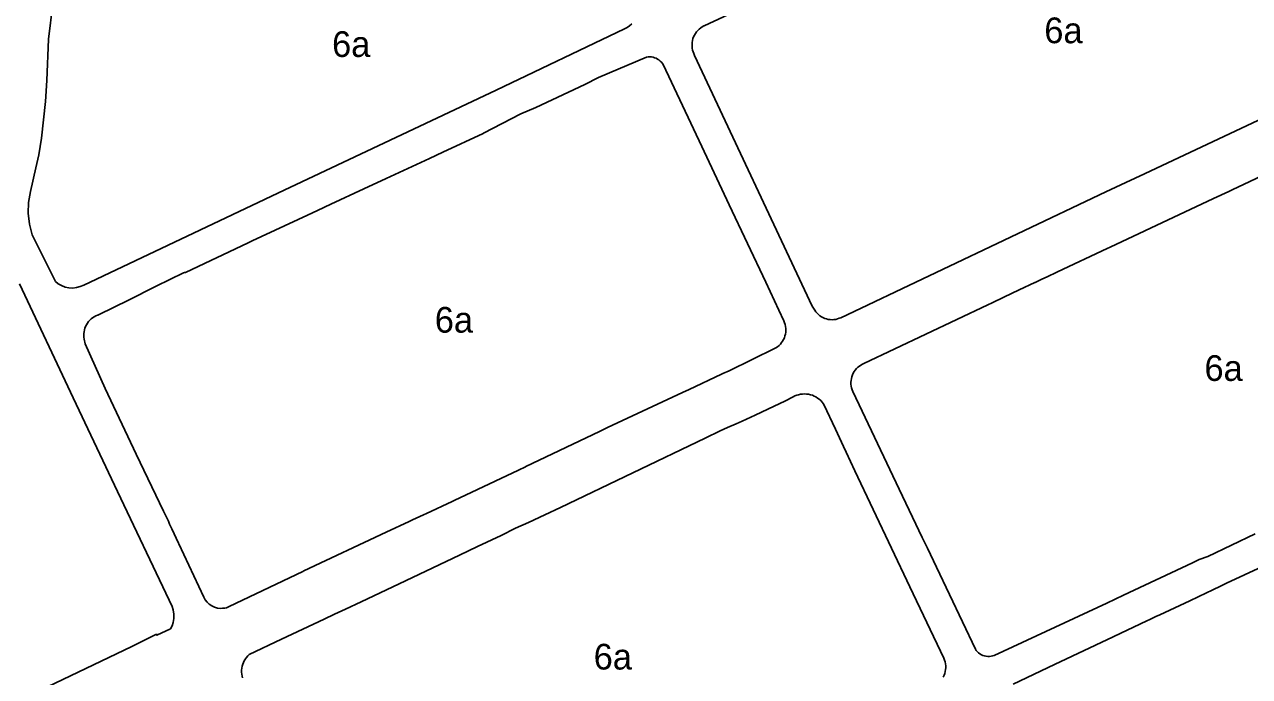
# Model space of a CAD drawing. Extents: x 598968 to 613553, y 4409678 to 4430833.
# Drawn here: x 606081 to 606653, y 4415842 to 4416147 of the extents above; entities that cross this region are included whole.
import ezdxf

# ---------------------------------------------------------------- set-up
doc = ezdxf.new("R2010")
doc.units = 0
doc.layers.add('1', color=7, linetype='Continuous')
doc.layers.add('Polígon industrial de Maó (naus i rafals) - ANNEX III D', color=7, linetype='Continuous')

msp = doc.modelspace()

# ---------------------------------------------------------------- linework, layer by layer
at = {"layer": '1'}
for points in [[(606714.9936, 4416129.6429), (606603.6249, 4416077.1617), (606594.915, 4416073.0516), (606585.6851, 4416068.7015), (606461.9065, 4416010.0001), (606461.2565, 4416009.7101), (606460.4265, 4416009.4301), (606459.5765, 4416009.2301), (606458.7165, 4416009.1101), (606457.8465, 4416009.0601), (606456.9766, 4416009.1001), (606456.1166, 4416009.2101), (606455.2666, 4416009.4), (606454.4366, 4416009.67), (606453.6366, 4416010.02), (606452.8666, 4416010.44), (606452.1466, 4416010.92), (606451.4766, 4416011.47), (606450.8466, 4416012.0799), (606450.2866, 4416012.7499), (606449.7866, 4416013.4599), (606448.6166, 4416015.3899), (606393.7268, 4416132.4777), (606393.3268, 4416133.2776), (606393.0168, 4416134.1176), (606392.7668, 4416134.9776), (606392.6067, 4416135.8576), (606392.5167, 4416136.7476), (606392.5167, 4416137.6376), (606392.5867, 4416138.5276), (606392.7467, 4416139.4076), (606392.9767, 4416140.2776), (606393.2867, 4416141.1176), (606393.6667, 4416141.9276), (606394.1167, 4416142.6976), (606394.6367, 4416143.4276), (606395.2267, 4416144.1076), (606395.8667, 4416144.7276), (606396.5567, 4416145.2876), (606397.2966, 4416145.7876), (606398.0866, 4416146.2276), (606398.1466, 4416146.2576), (606476.6657, 4416182.9285)], [(606364.3719, 4416147.226), (606363.3838, 4416146.2391), (606362.2488, 4416145.4255), (606360.997, 4416144.8067), (606301.1777, 4416116.2463), (606202.1687, 4416069.5752), (606108.6759, 4416025.2142), (606107.0466, 4416024.4959), (606105.3254, 4416024.04), (606103.5542, 4416023.8577), (606101.7762, 4416023.9534), (606100.0348, 4416024.3246), (606098.3724, 4416024.9625), (606096.8296, 4416025.8515), (606095.444, 4416026.9697), (606084.6908, 4416048.6742), (606083.329, 4416053.6255), (606082.7159, 4416058.724), (606082.8651, 4416063.857), (606083.7731, 4416068.9113), (606086.3129, 4416079.9566), (606087.6797, 4416086.0228), (606089.0208, 4416093.7918), (606090.8736, 4416110.9763), (606091.3879, 4416120.7991), (606092.2295, 4416140.1127), (606094.2594, 4416156.5825)], [(606655.2851, 4415909.1644), (606633.1953, 4415898.5342), (606629.2354, 4415897.0641), (606629.1654, 4415897.0441), (606626.0954, 4415895.6041), (606593.8857, 4415880.3836), (606586.0958, 4415876.7035), (606533.5164, 4415852.2929), (606532.7964, 4415852.0629), (606532.0364, 4415851.9129), (606531.2664, 4415851.8429), (606530.4964, 4415851.8529), (606529.7364, 4415851.9429), (606528.9765, 4415852.1029), (606528.2465, 4415852.3529), (606527.5465, 4415852.6628), (606526.8865, 4415853.0528), (606526.2565, 4415853.5128), (606525.6865, 4415854.0328), (606525.1765, 4415854.6028), (606524.7265, 4415855.2328), (606506.5265, 4415893.5721), (606502.3565, 4415902.352), (606499.9365, 4415907.4319), (606495.4665, 4415916.8517), (606489.2465, 4415929.9015), (606467.5166, 4415975.5806), (606467.1866, 4415976.3906), (606466.9366, 4415977.2406), (606466.7666, 4415978.1006), (606466.6666, 4415978.9806), (606466.6566, 4415979.8606), (606466.7166, 4415980.7405), (606466.8666, 4415981.6105), (606467.0866, 4415982.4605), (606467.3865, 4415983.2905), (606467.7565, 4415984.0905), (606468.2065, 4415984.8505), (606468.7165, 4415985.5705), (606469.2865, 4415986.2305), (606469.9265, 4415986.8505), (606470.6065, 4415987.4005), (606471.3465, 4415987.8905), (606472.1165, 4415988.3106), (606472.6165, 4415988.5406), (606530.4958, 4416015.9912), (606532.6058, 4416016.9912), (606537.9558, 4416019.5313), (606545.1757, 4416022.9614), (606552.4156, 4416026.3915), (606552.5956, 4416026.4815), (606555.5156, 4416027.8615), (606558.5355, 4416029.3015), (606562.4355, 4416031.1416), (606563.0955, 4416031.4516), (606586.3052, 4416042.3518), (606587.6752, 4416042.9918), (606603.805, 4416050.562), (606635.8947, 4416065.6324), (606642.9446, 4416068.9424), (606644.5646, 4416069.7025), (606726.6136, 4416108.3834)], [(606078.7075, 4416025.8831), (606103.7699, 4415972.6346), (606124.4582, 4415928.8511), (606148.533, 4415878.0414), (606149.8787, 4415875.2337), (606150.3831, 4415873.5761), (606150.7078, 4415871.5086), (606150.7243, 4415869.634), (606150.4163, 4415867.6769), (606149.8743, 4415866.151), (606149.1399, 4415864.7864), (606142.8299, 4415861.7363), (606142.6199, 4415862.1763), (606131.1401, 4415856.4662), (606073.9307, 4415829.0255)], [(606182.7796, 4415841.7872), (606182.5496, 4415842.6772), (606182.4096, 4415843.5972), (606182.3496, 4415844.5172), (606182.3596, 4415845.4472), (606182.4596, 4415846.3672), (606182.6296, 4415847.2772), (606182.8896, 4415848.1672), (606183.2196, 4415849.0272), (606183.6196, 4415849.8672), (606184.0896, 4415850.6572), (606184.6296, 4415851.4172), (606185.2296, 4415852.1172), (606185.8196, 4415852.6972), (606200.9894, 4415859.8473), (606220.8592, 4415869.2176), (606225.7691, 4415871.5276), (606230.8691, 4415873.9477), (606238.119, 4415877.3878), (606255.8689, 4415885.818), (606262.0688, 4415888.758), (606284.0786, 4415899.1984), (606292.4285, 4415903.1385), (606303.3884, 4415908.3186), (606310.1983, 4415911.7987), (606316.1983, 4415914.3688), (606323.7982, 4415917.9589), (606331.0781, 4415921.3889), (606398.5873, 4415953.7497), (606405.7272, 4415957.1898), (606409.0572, 4415958.6998), (606413.0471, 4415960.4399), (606415.9771, 4415961.7299), (606421.917, 4415964.53), (606430.8269, 4415968.7401), (606435.7869, 4415971.0801), (606439.6968, 4415973.0302), (606440.5168, 4415973.4402), (606441.3868, 4415973.7902), (606442.2668, 4415974.0602), (606443.1768, 4415974.2602), (606444.0968, 4415974.3702), (606445.0268, 4415974.4103), (606445.9568, 4415974.3603), (606446.8768, 4415974.2403), (606447.7868, 4415974.0403), (606448.6668, 4415973.7603), (606449.5268, 4415973.4003), (606450.3567, 4415972.9804), (606451.1367, 4415972.4804), (606451.8767, 4415971.9204), (606452.5667, 4415971.2904), (606453.1967, 4415970.6104), (606453.7667, 4415969.8804), (606454.0267, 4415969.5105), (606459.4267, 4415957.9707), (606463.2467, 4415949.7908), (606464.4367, 4415947.2609), (606468.5567, 4415938.441), (606494.1867, 4415884.3119), (606502.1066, 4415867.7323), (606510.0766, 4415851.0326), (606510.3966, 4415850.1726), (606510.6366, 4415849.2926), (606510.8066, 4415848.4026), (606510.8966, 4415847.4926), (606510.9066, 4415846.5826), (606510.8366, 4415845.6726), (606510.6866, 4415844.7726), (606510.4567, 4415843.8926), (606510.1567, 4415843.0327), (606509.7767, 4415842.2027)], [(606542.4164, 4415838.8932), (606561.6762, 4415848.0235), (606589.1059, 4415861.0338), (606589.3759, 4415861.1638), (606604.7557, 4415868.4539), (606606.1357, 4415869.114), (606609.0056, 4415870.474), (606610.8156, 4415871.324), (606624.7455, 4415877.8842), (606632.5954, 4415881.5843), (606635.1954, 4415882.8143), (606639.3553, 4415884.7743), (606641.9353, 4415885.9844), (606658.7351, 4415893.8947)]]:
    msp.add_lwpolyline(points, dxfattribs=at)
msp.add_lwpolyline([(606409.8568, 4416062.6987), (606426.9068, 4416026.5194), (606433.0368, 4416013.4896), (606435.4068, 4416008.4697), (606435.7368, 4416007.6397), (606435.9968, 4416006.7898), (606436.1768, 4416005.9198), (606436.2868, 4416005.0298), (606436.3068, 4416004.1398), (606436.2568, 4416003.2498), (606436.1168, 4416002.3698), (606435.9068, 4416001.5098), (606435.6168, 4416000.6698), (606435.2468, 4415999.8498), (606434.8168, 4415999.0798), (606434.3068, 4415998.3398), (606433.7368, 4415997.6598), (606433.1168, 4415997.0298), (606432.4368, 4415996.4498), (606431.7068, 4415995.9398), (606431.2968, 4415995.6998), (606409.8071, 4415985.1396), (606406.8371, 4415983.8795), (606406.337, 4415983.6448), (606391.1419, 4415976.5129), (606388.0774, 4415975.0793), (606353.0678, 4415958.6589), (606349.2878, 4415956.8889), (606315.0482, 4415940.5785), (606314.7782, 4415940.4385), (606311.4782, 4415938.8684), (606281.5185, 4415924.6681), (606280.6485, 4415924.2581), (606268.6687, 4415918.6579), (606267.2687, 4415918.0079), (606262.1387, 4415915.6179), (606260.5888, 4415914.8878), (606249.7989, 4415909.8477), (606211.4092, 4415891.8073), (606210.9054, 4415891.5658), (606176.5696, 4415875.1068), (606175.2556, 4415874.6075), (606174.4614, 4415874.4437), (606173.8788, 4415874.3235), (606173.4762, 4415874.306), (606172.4743, 4415874.2624), (606171.0781, 4415874.4256), (606169.7256, 4415874.8089), (606168.4514, 4415875.4025), (606167.2879, 4415876.1914), (606166.2648, 4415877.1554), (606165.4081, 4415878.2699), (606164.7397, 4415879.5065), (606153.0516, 4415904.4014), (606152.8897, 4415904.7462), (606149.7497, 4415911.486), (606148.7397, 4415913.656), (606148.1597, 4415914.926), (606145.9797, 4415919.6059), (606133.0897, 4415946.2654), (606118.7285, 4415977.0133), (606109.3798, 4415997.8445), (606108.8548, 4415999.9778), (606108.7818, 4416000.8353), (606108.6798, 4416002.0344), (606108.7998, 4416002.5844), (606108.8698, 4416003.4544), (606109.0298, 4416004.3044), (606109.2598, 4416005.1444), (606109.5698, 4416005.9544), (606109.9497, 4416006.7344), (606110.3997, 4416007.4844), (606110.9197, 4416008.1844), (606111.4997, 4416008.8244), (606112.1297, 4416009.4244), (606112.8197, 4416009.9544), (606113.5597, 4416010.4144), (606114.3297, 4416010.8144), (606115.1397, 4416011.1344), (606115.1997, 4416011.1644), (606123.1796, 4416015.1145), (606129.2195, 4416018.0846), (606142.5594, 4416024.6847), (606155.2892, 4416030.9749), (606155.6592, 4416031.1549), (606156.1992, 4416031.0849), (606185.3989, 4416044.9352), (606187.2889, 4416045.8352), (606213.0786, 4416057.8455), (606217.7386, 4416060.0156), (606224.0485, 4416062.9556), (606239.4383, 4416070.1258), (606249.7283, 4416074.9159), (606269.9781, 4416084.3462), (606276.198, 4416087.2362), (606295.0678, 4416095.9864), (606295.2478, 4416096.0764), (606312.6376, 4416105.1366), (606319.6675, 4416108.0667), (606342.4473, 4416118.887), (606348.8372, 4416122.167), (606371.257, 4416131.6373), (606372.017, 4416131.7373), (606372.7869, 4416131.7673), (606373.5569, 4416131.7173), (606374.3169, 4416131.5874), (606375.0569, 4416131.3874), (606375.7769, 4416131.0974), (606376.4569, 4416130.7474), (606377.0969, 4416130.3174), (606377.6969, 4416129.8274), (606378.2369, 4416129.2774), (606378.7169, 4416128.6775), (606378.9969, 4416128.2775), (606397.0568, 4416089.9082)], close=True, dxfattribs=at)
at = {"layer": 'Polígon industrial de Maó (naus i rafals) - ANNEX III D'}
for points in [[(606476.6657, 4416182.9285), (606398.1466, 4416146.2576), (606398.0866, 4416146.2276), (606397.2966, 4416145.7876), (606396.5567, 4416145.2876), (606395.8667, 4416144.7276), (606395.2267, 4416144.1076), (606394.6367, 4416143.4276), (606394.1167, 4416142.6976), (606393.6667, 4416141.9276), (606393.2867, 4416141.1176), (606392.9767, 4416140.2776), (606392.7467, 4416139.4076), (606392.5867, 4416138.5276), (606392.5167, 4416137.6376), (606392.5167, 4416136.7476), (606392.6067, 4416135.8576), (606392.7668, 4416134.9776), (606393.0168, 4416134.1176), (606393.3268, 4416133.2776), (606393.7268, 4416132.4777), (606448.6166, 4416015.3899), (606449.7866, 4416013.4599), (606450.2866, 4416012.7499), (606450.8466, 4416012.0799), (606451.4766, 4416011.47), (606452.1466, 4416010.92), (606452.8666, 4416010.44), (606453.6366, 4416010.02), (606454.4366, 4416009.67), (606455.2666, 4416009.4), (606456.1166, 4416009.2101), (606456.9766, 4416009.1001), (606457.8465, 4416009.0601), (606458.7165, 4416009.1101), (606459.5765, 4416009.2301), (606460.4265, 4416009.4301), (606461.2565, 4416009.7101), (606461.9065, 4416010.0001), (606585.6851, 4416068.7015), (606594.915, 4416073.0516), (606603.6249, 4416077.1617), (606714.9936, 4416129.6429)], [(606094.2594, 4416156.5825), (606092.2295, 4416140.1127), (606091.3879, 4416120.7991), (606090.8736, 4416110.9763), (606089.0208, 4416093.7918), (606087.6797, 4416086.0228), (606086.3129, 4416079.9566), (606083.7731, 4416068.9113), (606082.8651, 4416063.857), (606082.7159, 4416058.724), (606083.329, 4416053.6255), (606084.6908, 4416048.6742), (606095.444, 4416026.9697), (606096.8296, 4416025.8515), (606098.3724, 4416024.9625), (606100.0348, 4416024.3246), (606101.7762, 4416023.9534), (606103.5542, 4416023.8577), (606105.3254, 4416024.04), (606107.0466, 4416024.4959), (606108.6759, 4416025.2142), (606202.1687, 4416069.5752), (606301.1777, 4416116.2463), (606360.997, 4416144.8067), (606362.2488, 4416145.4255), (606363.3838, 4416146.2391), (606364.3719, 4416147.226)], [(606726.6136, 4416108.3834), (606644.5646, 4416069.7025), (606642.9446, 4416068.9424), (606635.8947, 4416065.6324), (606603.805, 4416050.562), (606587.6752, 4416042.9918), (606586.3052, 4416042.3518), (606563.0955, 4416031.4516), (606562.4355, 4416031.1416), (606558.5355, 4416029.3015), (606555.5156, 4416027.8615), (606552.5956, 4416026.4815), (606552.4156, 4416026.3915), (606545.1757, 4416022.9614), (606537.9558, 4416019.5313), (606532.6058, 4416016.9912), (606530.4958, 4416015.9912), (606472.6165, 4415988.5406), (606472.1165, 4415988.3106), (606471.3465, 4415987.8905), (606470.6065, 4415987.4005), (606469.9265, 4415986.8505), (606469.2865, 4415986.2305), (606468.7165, 4415985.5705), (606468.2065, 4415984.8505), (606467.7565, 4415984.0905), (606467.3865, 4415983.2905), (606467.0866, 4415982.4605), (606466.8666, 4415981.6105), (606466.7166, 4415980.7405), (606466.6566, 4415979.8606), (606466.6666, 4415978.9806), (606466.7666, 4415978.1006), (606466.9366, 4415977.2406), (606467.1866, 4415976.3906), (606467.5166, 4415975.5806), (606489.2465, 4415929.9015), (606495.4665, 4415916.8517), (606499.9365, 4415907.4319), (606502.3565, 4415902.352), (606506.5265, 4415893.5721), (606524.7265, 4415855.2328), (606525.1765, 4415854.6028), (606525.6865, 4415854.0328), (606526.2565, 4415853.5128), (606526.8865, 4415853.0528), (606527.5465, 4415852.6628), (606528.2465, 4415852.3529), (606528.9765, 4415852.1029), (606529.7364, 4415851.9429), (606530.4964, 4415851.8529), (606531.2664, 4415851.8429), (606532.0364, 4415851.9129), (606532.7964, 4415852.0629), (606533.5164, 4415852.2929), (606586.0958, 4415876.7035), (606593.8857, 4415880.3836), (606626.0954, 4415895.6041), (606629.1654, 4415897.0441), (606629.2354, 4415897.0641), (606633.1953, 4415898.5342), (606655.2851, 4415909.1644)], [(606073.9307, 4415829.0255), (606131.1401, 4415856.4662), (606142.6199, 4415862.1763), (606142.8299, 4415861.7363), (606149.1399, 4415864.7864), (606149.8743, 4415866.151), (606150.4163, 4415867.6769), (606150.7243, 4415869.634), (606150.7078, 4415871.5086), (606150.3831, 4415873.5761), (606149.8787, 4415875.2337), (606148.533, 4415878.0414), (606124.4582, 4415928.8511), (606103.7699, 4415972.6346), (606078.7075, 4416025.8831)], [(606509.7767, 4415842.2027), (606510.1567, 4415843.0327), (606510.4567, 4415843.8926), (606510.6866, 4415844.7726), (606510.8366, 4415845.6726), (606510.9066, 4415846.5826), (606510.8966, 4415847.4926), (606510.8066, 4415848.4026), (606510.6366, 4415849.2926), (606510.3966, 4415850.1726), (606510.0766, 4415851.0326), (606502.1066, 4415867.7323), (606494.1867, 4415884.3119), (606468.5567, 4415938.441), (606464.4367, 4415947.2609), (606463.2467, 4415949.7908), (606459.4267, 4415957.9707), (606454.0267, 4415969.5105), (606453.7667, 4415969.8804), (606453.1967, 4415970.6104), (606452.5667, 4415971.2904), (606451.8767, 4415971.9204), (606451.1367, 4415972.4804), (606450.3567, 4415972.9804), (606449.5268, 4415973.4003), (606448.6668, 4415973.7603), (606447.7868, 4415974.0403), (606446.8768, 4415974.2403), (606445.9568, 4415974.3603), (606445.0268, 4415974.4103), (606444.0968, 4415974.3702), (606443.1768, 4415974.2602), (606442.2668, 4415974.0602), (606441.3868, 4415973.7902), (606440.5168, 4415973.4402), (606439.6968, 4415973.0302), (606435.7869, 4415971.0801), (606430.8269, 4415968.7401), (606421.917, 4415964.53), (606415.9771, 4415961.7299), (606413.0471, 4415960.4399), (606409.0572, 4415958.6998), (606405.7272, 4415957.1898), (606398.5873, 4415953.7497), (606331.0781, 4415921.3889), (606323.7982, 4415917.9589), (606316.1983, 4415914.3688), (606310.1983, 4415911.7987), (606303.3884, 4415908.3186), (606292.4285, 4415903.1385), (606284.0786, 4415899.1984), (606262.0688, 4415888.758), (606255.8689, 4415885.818), (606238.119, 4415877.3878), (606230.8691, 4415873.9477), (606225.7691, 4415871.5276), (606220.8592, 4415869.2176), (606200.9894, 4415859.8473), (606185.8196, 4415852.6972), (606185.2296, 4415852.1172), (606184.6296, 4415851.4172), (606184.0896, 4415850.6572), (606183.6196, 4415849.8672), (606183.2196, 4415849.0272), (606182.8896, 4415848.1672), (606182.6296, 4415847.2772), (606182.4596, 4415846.3672), (606182.3596, 4415845.4472), (606182.3496, 4415844.5172), (606182.4096, 4415843.5972), (606182.5496, 4415842.6772), (606182.7796, 4415841.7872)], [(606658.7351, 4415893.8947), (606641.9353, 4415885.9844), (606639.3553, 4415884.7743), (606635.1954, 4415882.8143), (606632.5954, 4415881.5843), (606624.7455, 4415877.8842), (606610.8156, 4415871.324), (606609.0056, 4415870.474), (606606.1357, 4415869.114), (606604.7557, 4415868.4539), (606589.3759, 4415861.1638), (606589.1059, 4415861.0338), (606561.6762, 4415848.0235), (606542.4164, 4415838.8932)]]:
    msp.add_lwpolyline(points, dxfattribs=at)
msp.add_lwpolyline([(606409.8568, 4416062.6987), (606397.0568, 4416089.9082), (606378.9969, 4416128.2775), (606378.7169, 4416128.6775), (606378.2369, 4416129.2774), (606377.6969, 4416129.8274), (606377.0969, 4416130.3174), (606376.4569, 4416130.7474), (606375.7769, 4416131.0974), (606375.0569, 4416131.3874), (606374.3169, 4416131.5874), (606373.5569, 4416131.7173), (606372.7869, 4416131.7673), (606372.017, 4416131.7373), (606371.257, 4416131.6373), (606348.8372, 4416122.167), (606342.4473, 4416118.887), (606319.6675, 4416108.0667), (606312.6376, 4416105.1366), (606295.2478, 4416096.0764), (606295.0678, 4416095.9864), (606276.198, 4416087.2362), (606269.9781, 4416084.3462), (606249.7283, 4416074.9159), (606239.4383, 4416070.1258), (606224.0485, 4416062.9556), (606217.7386, 4416060.0156), (606213.0786, 4416057.8455), (606187.2889, 4416045.8352), (606185.3989, 4416044.9352), (606156.1992, 4416031.0849), (606155.6592, 4416031.1549), (606155.2892, 4416030.9749), (606142.5594, 4416024.6847), (606129.2195, 4416018.0846), (606123.1796, 4416015.1145), (606115.1997, 4416011.1644), (606115.1397, 4416011.1344), (606114.3297, 4416010.8144), (606113.5597, 4416010.4144), (606112.8197, 4416009.9544), (606112.1297, 4416009.4244), (606111.4997, 4416008.8244), (606110.9197, 4416008.1844), (606110.3997, 4416007.4844), (606109.9497, 4416006.7344), (606109.5698, 4416005.9544), (606109.2598, 4416005.1444), (606109.0298, 4416004.3044), (606108.8698, 4416003.4544), (606108.7998, 4416002.5844), (606108.6798, 4416002.0344), (606108.7818, 4416000.8353), (606108.8548, 4415999.9778), (606109.3798, 4415997.8445), (606118.7285, 4415977.0133), (606133.0897, 4415946.2654), (606145.9797, 4415919.6059), (606148.1597, 4415914.926), (606148.7397, 4415913.656), (606149.7497, 4415911.486), (606152.8897, 4415904.7462), (606153.0516, 4415904.4014), (606164.7397, 4415879.5065), (606165.4081, 4415878.2699), (606166.2648, 4415877.1554), (606167.2879, 4415876.1914), (606168.4514, 4415875.4025), (606169.7256, 4415874.8089), (606171.0781, 4415874.4256), (606172.4743, 4415874.2624), (606173.4762, 4415874.306), (606173.8788, 4415874.3235), (606174.4614, 4415874.4437), (606175.2556, 4415874.6075), (606176.5696, 4415875.1068), (606210.9054, 4415891.5658), (606211.4092, 4415891.8073), (606249.7989, 4415909.8477), (606260.5888, 4415914.8878), (606262.1387, 4415915.6179), (606267.2687, 4415918.0079), (606268.6687, 4415918.6579), (606280.6485, 4415924.2581), (606281.5185, 4415924.6681), (606311.4782, 4415938.8684), (606314.7782, 4415940.4385), (606315.0482, 4415940.5785), (606349.2878, 4415956.8889), (606353.0678, 4415958.6589), (606388.0774, 4415975.0793), (606391.1419, 4415976.5129), (606406.337, 4415983.6448), (606406.8371, 4415983.8795), (606409.8071, 4415985.1396), (606431.2968, 4415995.6998), (606431.7068, 4415995.9398), (606432.4368, 4415996.4498), (606433.1168, 4415997.0298), (606433.7368, 4415997.6598), (606434.3068, 4415998.3398), (606434.8168, 4415999.0798), (606435.2468, 4415999.8498), (606435.6168, 4416000.6698), (606435.9068, 4416001.5098), (606436.1168, 4416002.3698), (606436.2568, 4416003.2498), (606436.3068, 4416004.1398), (606436.2868, 4416005.0298), (606436.1768, 4416005.9198), (606435.9968, 4416006.7898), (606435.7368, 4416007.6397), (606435.4068, 4416008.4697), (606433.0368, 4416013.4896), (606426.9068, 4416026.5194)], close=True, dxfattribs=at)

# ---------------------------------------------------------------- texts
for p in [(606556.9052, 4416138.1503), (606224.5603, 4416131.733), (606272.4933, 4416003.0148), (606631.635, 4415980.4781), (606346.6281, 4415845.74)]:
    msp.add_text('6a', height=12, dxfattribs=at).set_placement(p)

doc.saveas('drawing.dxf')
